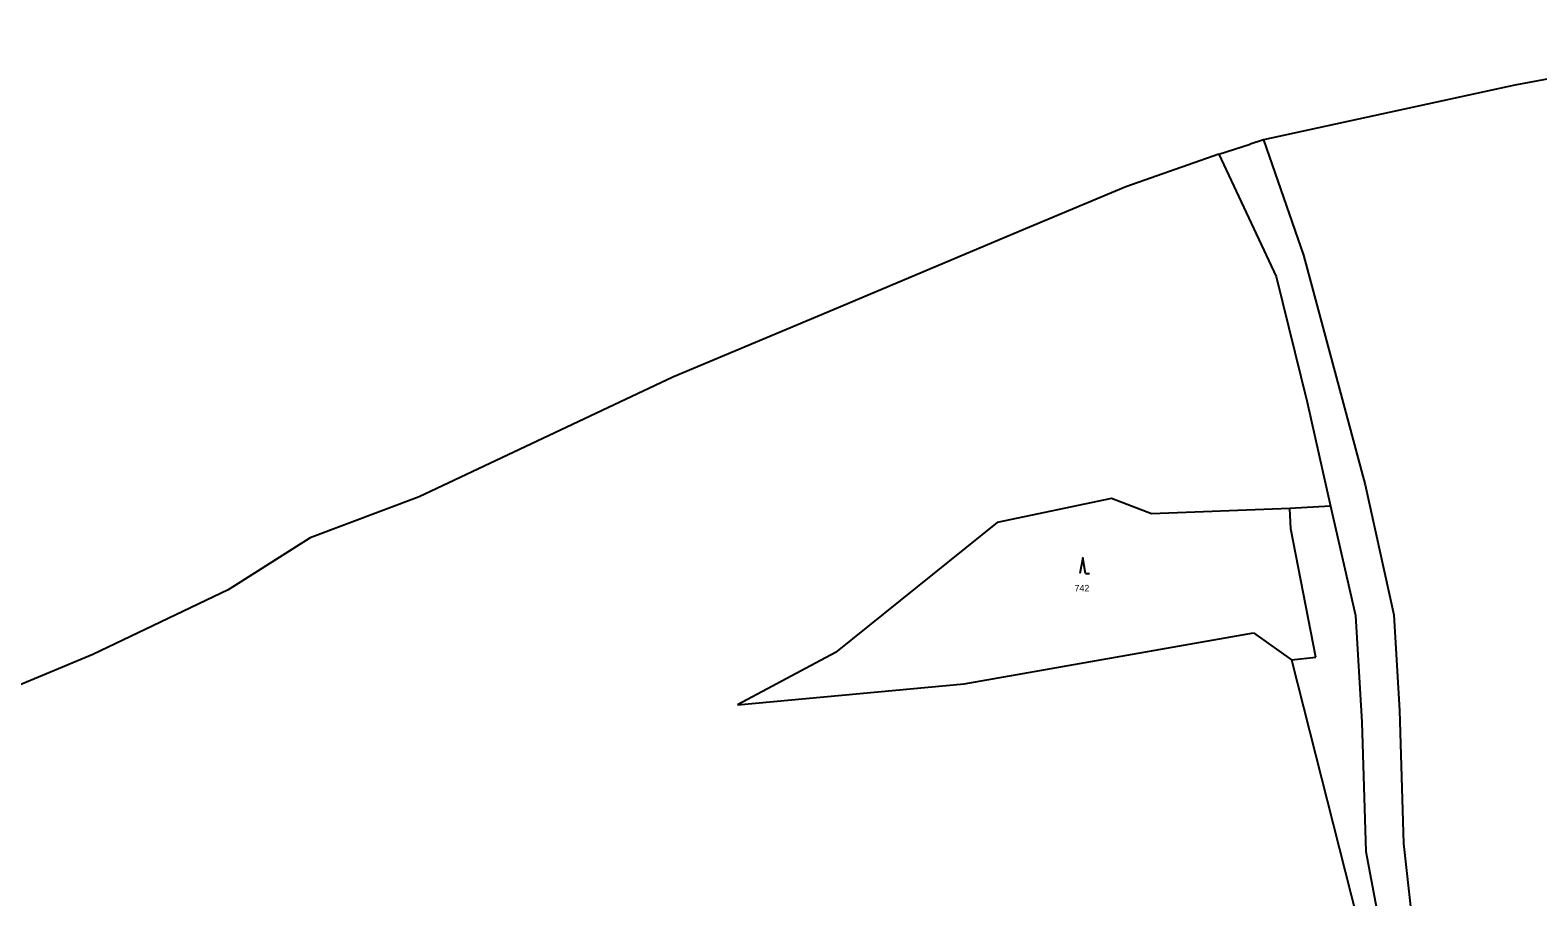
# Model space of a CAD drawing. Extents: x -744132 to -742433, y -984679 to -982287.
# Drawn here: x -743440.4 to -743052.8, y -982572.6 to -982349.6 of the extents above; entities that cross this region are included whole.
import ezdxf

# ---------------------------------------------------------------- set-up
doc = ezdxf.new("R2010")
doc.units = 0
doc.header["$LTSCALE"] = 0.68
doc.layers.add('1', color=7, linetype='Continuous', lineweight=25)
doc.layers.add('3', color=7, linetype='Continuous', lineweight=25)
doc.layers.add('2', color=7, linetype='Continuous')

msp = doc.modelspace()

# ---------------------------------------------------------------- linework, layer by layer
at = {"layer": '1'}
for p, q in [((-742983.25, -982349.62), (-743058.69, -982363.77)), ((-743058.69, -982363.77), (-743123.36, -982377.82)), ((-743134.78, -982381.53), (-743126.77, -982378.93)), ((-743123.36, -982377.82), (-743126.77, -982378.93)), ((-743123.36, -982377.82), (-743113.03, -982407.51)), ((-743134.78, -982381.53), (-743158.72, -982389.9)), ((-743134.78, -982381.53), (-743120.04, -982412.95)), ((-743158.72, -982389.9), (-743186.13, -982401.44)), ((-743186.13, -982401.44), (-743235.36, -982422.14)), ((-743113.03, -982407.51), (-743097.24, -982466.55)), ((-743120.04, -982412.95), (-743112.15, -982445.27)), ((-743235.36, -982422.14), (-743275.14, -982438.87)), ((-743275.14, -982438.87), (-743314.57, -982457.52)), ((-743112.15, -982445.27), (-743106.12, -982472.06)), ((-743314.57, -982457.52), (-743340.37, -982469.64)), ((-743097.24, -982466.55), (-743089.85, -982500.01)), ((-743340.37, -982469.64), (-743368.4, -982480.17)), ((-743162.41, -982470.13), (-743191.79, -982476.3)), ((-743152.16, -982474.07), (-743162.41, -982470.13)), ((-743116.57, -982472.62), (-743152.16, -982474.07)), ((-743106.12, -982472.06), (-743116.57, -982472.62)), ((-743116.32, -982477.85), (-743116.57, -982472.62)), ((-743106.12, -982472.06), (-743099.66, -982500.18)), ((-743191.79, -982476.3), (-743233.39, -982509.68)), ((-743368.4, -982480.17), (-743385.3, -982490.92)), ((-743109.85, -982510.89), (-743116.32, -982477.85)), ((-743385.3, -982490.92), (-743389.52, -982493.61)), ((-743389.52, -982493.61), (-743424.28, -982510.21)), ((-743099.66, -982500.18), (-743098.07, -982527.62)), ((-743089.85, -982500.01), (-743088.39, -982524.64)), ((-743200.31, -982517.74), (-743125.87, -982504.6)), ((-743125.87, -982504.6), (-743116.14, -982511.59)), ((-743424.28, -982510.21), (-743453.99, -982522.61)), ((-743233.39, -982509.68), (-743258.53, -982523.18)), ((-743116.14, -982511.59), (-743109.85, -982510.89)), ((-743116.14, -982511.59), (-743099.24, -982578.2)), ((-743258.53, -982523.18), (-743200.31, -982517.74)), ((-743098.07, -982527.62), (-743097.04, -982560.9)), ((-743088.39, -982524.64), (-743087.31, -982558.84)), ((-743097.04, -982560.9), (-743091.09, -982592.29)), ((-743087.31, -982558.84), (-743084.83, -982581.2))]:
    msp.add_line(p, q, dxfattribs=at)
at = {"layer": '3'}
msp.add_line((-743169.06, -982489.38), (-743168.064, -982489.38), dxfattribs=at)
msp.add_lwpolyline([(-743169.06, -982489.38), (-743169.81, -982485.38), (-743170.56, -982489.38)], dxfattribs=at)

# ---------------------------------------------------------------- texts
at = {"layer": '2'}
msp.add_text('742', height=1.7, dxfattribs=at).set_placement((-743171.91, -982494.005))

doc.saveas('drawing.dxf')
